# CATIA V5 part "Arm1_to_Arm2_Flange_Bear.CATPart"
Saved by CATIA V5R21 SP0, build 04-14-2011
Part number: Arm1_to_Arm2_Flange_Bear
Bounding box of the stored display mesh (mm): x -7.8 to 7.8, y -7.8 to 7.8, z 0 to 4
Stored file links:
  C:\Users\水心\Desktop\Arm_Detailed_Design_Assembly_Manu\Arm1_to_Arm2_Flange_Bear.CATPart
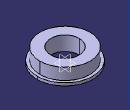
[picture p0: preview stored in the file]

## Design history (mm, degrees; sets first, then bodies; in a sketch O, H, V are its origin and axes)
Body1 (main body)
  Sketch1 on xy-plane, origin (0, 0, 0), H (1, 0, 0), V (0, 1, 0)
    circle A1 centre (0, 0) radius 7.8
    radius A1 = 7.8
  Pad1: profile Sketch1, direction (0, 0, 1), length 0.78
  Sketch2 on end face of Pad1, origin (0, 0, 0.78), H (1, 0, 0), V (0, 1, 0)
    circle A1 centre (0, 0) radius 7
    radius A1 = 7
  Pad2: profile Sketch2, direction (0, 0, 1), length 3.22
  Sketch3 on end face of Pad2, origin (0, 0, 4), H (1, 0, 0), V (0, 1, 0)
    circle A1 centre (0, 0) radius 4
    radius A1 = 4
  Pocket1: profile Sketch3, direction (0, 0, -1), through (limit type 3)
